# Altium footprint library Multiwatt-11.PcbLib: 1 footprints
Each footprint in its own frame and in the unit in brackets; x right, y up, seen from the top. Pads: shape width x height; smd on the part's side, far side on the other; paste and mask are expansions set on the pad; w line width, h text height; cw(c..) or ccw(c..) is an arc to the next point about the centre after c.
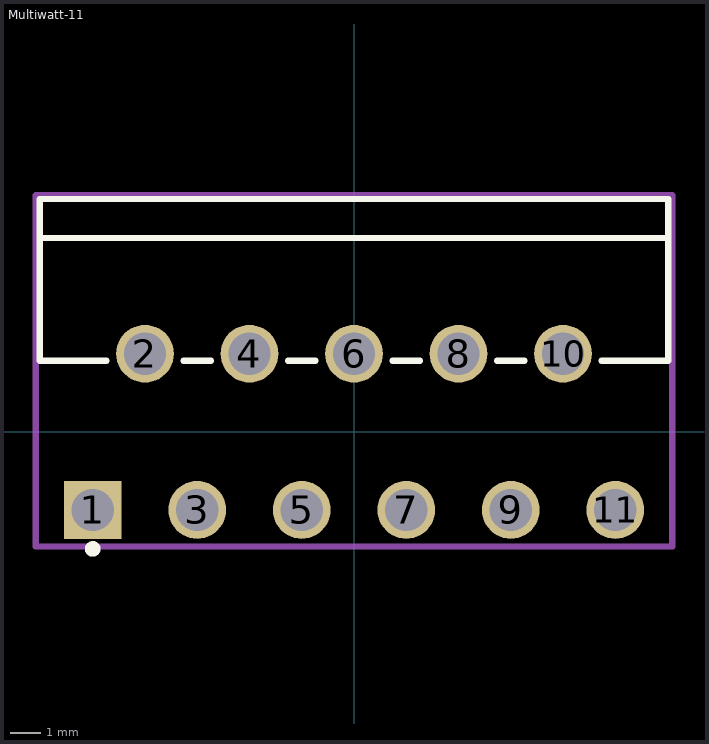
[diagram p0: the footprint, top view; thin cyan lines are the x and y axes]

## Multiwatt-11 [mil]
pads (11):
  rect 74x74 / inner round 60 / far side rect 74x74 hole 54: 1(-334.65,-100)
  round 74 / inner round 60 / far side round 74 hole 54: 2(-267.72,100) 3(-200.79,-100) 4(-133.86,100) 5(-66.93,-100) 6(0,100) 7(66.93,-100) 8(133.86,100) 9(200.79,-100) 10(267.72,100) 11(334.65,-100)
Top Overlay:
  circle w10: c-334.65,-150 r5
  lines w7.87: -397.5,248 397.5,248 ; -317,91 -402.5,91 -402.5,298 402.5,298 402.5,91 317,91 ; -218.43,91 -183.14,91 ; -84.57,91 -49.28,91 ; 49.28,91 84.57,91 ; 183.14,91 218.43,91
Mechanical 15:
  lines w7.87: -407.5,-147 407.5,-147 407.5,303 -407.5,303 -407.5,-147
3D body "Multiwatt11_V_STM.step": height 984.49, standoff -90.51, extent -397.5,-116.5 397.5,295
